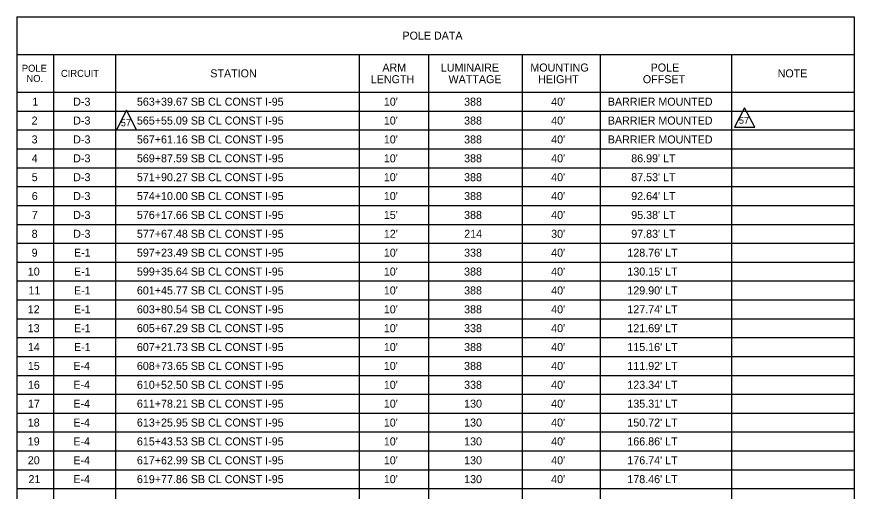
# Model space of a CAD drawing. Extents: x -818.1 to -802.4, y -2221.2 to -2187.7.
# Drawn here: x -817.38 to -810.06, y -2191.84 to -2187.69 of the extents above; entities that cross this region are included whole.
import ezdxf

# ---------------------------------------------------------------- set-up
doc = ezdxf.new("R2010")
doc.units = 0
for name, color, linetype in [('Cloud_dp', 7, 'Continuous'), ('SumBoxBorder_dp', 7, 'Continuous'), ('SumBoxLines_dp', 7, 'Continuous'), ('SumBoxLinesMin_dp', 7, 'Continuous'), ('TextLabel', 7, 'Continuous')]:
    doc.layers.add(name, color=color, linetype=linetype)

msp = doc.modelspace()

# ---------------------------------------------------------------- linework, layer by layer
at = {"layer": 'Cloud_dp'}
for points in [[(-816.4166, -2188.5096), (-816.5046, -2188.6791), (-816.3286, -2188.6791)], [(-811.0144, -2188.4885), (-811.1024, -2188.6581), (-810.9263, -2188.6581)]]:
    msp.add_lwpolyline(points, close=True, dxfattribs=at)
at = {"layer": 'SumBoxBorder_dp'}
for p, q in [((-817.3764, -2187.6917), (-810.0564, -2187.6917)), ((-817.3764, -2187.6917), (-817.3764, -2195.9417)), ((-810.0564, -2187.6917), (-810.0564, -2195.9417)), ((-810.0564, -2187.6917), (-810.0564, -2195.9417)), ((-817.3764, -2188.0217), (-810.0564, -2188.0217)), ((-817.3764, -2188.0217), (-810.0564, -2188.0217))]:
    msp.add_line(p, q, dxfattribs=at)
at = {"layer": 'SumBoxLines_dp'}
for p, q in [((-817.0539, -2188.0217), (-817.0539, -2195.9417)), ((-817.0539, -2188.0217), (-817.0539, -2195.9417)), ((-816.5139, -2188.0217), (-816.5139, -2195.9417)), ((-816.5139, -2188.0217), (-816.5139, -2195.9417)), ((-814.3839, -2188.0217), (-814.3839, -2193.9617)), ((-814.3839, -2188.0217), (-814.3839, -2195.9417)), ((-813.7764, -2188.0217), (-813.7764, -2195.9417)), ((-813.7764, -2188.0217), (-813.7764, -2195.9417)), ((-812.9589, -2188.0217), (-812.9589, -2195.9417)), ((-812.9589, -2188.0217), (-812.9589, -2195.9417)), ((-812.2764, -2188.0217), (-812.2764, -2195.9417)), ((-812.2764, -2188.0217), (-812.2764, -2195.9417)), ((-811.1289, -2188.0217), (-811.1289, -2195.9417)), ((-811.1289, -2188.0217), (-811.1289, -2195.9417)), ((-817.3764, -2188.3517), (-810.0564, -2188.3517))]:
    msp.add_line(p, q, dxfattribs=at)
at = {"layer": 'SumBoxLinesMin_dp'}
for p, q in [((-817.3764, -2188.3517), (-810.0564, -2188.3517)), ((-817.3764, -2188.5167), (-810.0564, -2188.5167)), ((-817.3764, -2188.5167), (-810.0564, -2188.5167)), ((-817.3764, -2188.6817), (-810.0564, -2188.6817)), ((-817.3764, -2188.6817), (-810.0564, -2188.6817)), ((-817.3764, -2188.8467), (-810.0564, -2188.8467)), ((-817.3764, -2188.8467), (-810.0564, -2188.8467)), ((-817.3764, -2189.0117), (-810.0564, -2189.0117)), ((-817.3764, -2189.0117), (-810.0564, -2189.0117)), ((-817.3764, -2189.1767), (-810.0564, -2189.1767)), ((-817.3764, -2189.1767), (-810.0564, -2189.1767)), ((-817.3764, -2189.3417), (-810.0564, -2189.3417)), ((-817.3764, -2189.3417), (-810.0564, -2189.3417)), ((-817.3764, -2189.5067), (-810.0564, -2189.5067)), ((-817.3764, -2189.5067), (-810.0564, -2189.5067)), ((-817.3764, -2189.6717), (-810.0564, -2189.6717)), ((-817.3764, -2189.6717), (-810.0564, -2189.6717)), ((-817.3764, -2189.8367), (-810.0564, -2189.8367)), ((-817.3764, -2189.8367), (-810.0564, -2189.8367)), ((-817.3764, -2190.0017), (-810.0564, -2190.0017)), ((-817.3764, -2190.0017), (-810.0564, -2190.0017)), ((-817.3764, -2190.1667), (-810.0564, -2190.1667)), ((-817.3764, -2190.1667), (-810.0564, -2190.1667)), ((-817.3764, -2190.3317), (-810.0564, -2190.3317)), ((-817.3764, -2190.3317), (-810.0564, -2190.3317)), ((-817.3764, -2190.4967), (-810.0564, -2190.4967)), ((-817.3764, -2190.4967), (-810.0564, -2190.4967)), ((-817.3764, -2190.6617), (-810.0564, -2190.6617)), ((-817.3764, -2190.6617), (-810.0564, -2190.6617)), ((-817.3764, -2190.8267), (-810.0564, -2190.8267)), ((-817.3764, -2190.8267), (-810.0564, -2190.8267)), ((-817.3764, -2190.9917), (-810.0564, -2190.9917)), ((-817.3764, -2190.9917), (-810.0564, -2190.9917)), ((-817.3764, -2191.1567), (-810.0564, -2191.1567)), ((-817.3764, -2191.1567), (-810.0564, -2191.1567)), ((-817.3764, -2191.3217), (-810.0564, -2191.3217)), ((-817.3764, -2191.3217), (-810.0564, -2191.3217)), ((-817.3764, -2191.4867), (-810.0564, -2191.4867)), ((-817.3764, -2191.4867), (-810.0564, -2191.4867)), ((-817.3764, -2191.6517), (-810.0564, -2191.6517)), ((-817.3764, -2191.6517), (-810.0564, -2191.6517)), ((-817.3764, -2191.8167), (-810.0564, -2191.8167)), ((-817.3764, -2191.8167), (-810.0564, -2191.8167))]:
    msp.add_line(p, q, dxfattribs=at)

# ---------------------------------------------------------------- texts
at = {"layer": 'Cloud_dp'}
for p in [(-816.4673, -2188.6489), (-811.0651, -2188.6279)]:
    msp.add_text('57', height=0.06, dxfattribs=at).set_placement(p)
at = {"layer": 'TextLabel'}
for s, height, p in [('POLE DATA', 0.07, (-814.0053, -2187.8917)), ('POLE', 0.06125, (-817.3318, -2188.1727)), ('CIRCUIT', 0.06125, (-816.9898, -2188.2173)), ('STATION', 0.07, (-815.6847, -2188.2217)), ('ARM', 0.07, (-814.1806, -2188.1707)), ('LUMINAIRE', 0.07, (-813.6703, -2188.1707)), ('MOUNTING', 0.07, (-812.8873, -2188.1707)), ('POLE', 0.07, (-811.8359, -2188.1707)), ('NOTE', 0.07, (-810.7259, -2188.2217)), ('NO.', 0.06125, (-817.2918, -2188.2619)), ('LENGTH', 0.07, (-814.2821, -2188.2727)), ('WATTAGE', 0.07, (-813.6025, -2188.2727)), ('HEIGHT', 0.07, (-812.8191, -2188.2727)), ('OFFSET', 0.07, (-811.9041, -2188.2727)), ('1', 0.07, (-817.2398, -2188.4692)), ('D-3', 0.07, (-816.8831, -2188.4692)), ('563+39.67 SB CL CONST I-95', 0.07, (-816.3263, -2188.4692)), ("10'", 0.07, (-814.1681, -2188.4692)), ('388', 0.07, (-813.4665, -2188.4692)), ("40'", 0.07, (-812.7056, -2188.4692)), ('BARRIER MOUNTED', 0.07, (-812.2105, -2188.4692)), ('2', 0.07, (-817.2465, -2188.6342)), ('D-3', 0.07, (-816.8831, -2188.6342)), ('565+55.09 SB CL CONST I-95', 0.07, (-816.3263, -2188.6342)), ("10'", 0.07, (-814.1681, -2188.6342)), ('388', 0.07, (-813.4665, -2188.6342)), ("40'", 0.07, (-812.7056, -2188.6342)), ('BARRIER MOUNTED', 0.07, (-812.2105, -2188.6342)), ('3', 0.07, (-817.2466, -2188.7992)), ('D-3', 0.07, (-816.8831, -2188.7992)), ('567+61.16 SB CL CONST I-95', 0.07, (-816.3263, -2188.7992)), ("10'", 0.07, (-814.1681, -2188.7992)), ('388', 0.07, (-813.4665, -2188.7992)), ("40'", 0.07, (-812.7056, -2188.7992)), ('BARRIER MOUNTED', 0.07, (-812.2105, -2188.7992)), ('4', 0.07, (-817.2452, -2188.9642)), ('D-3', 0.07, (-816.8831, -2188.9642)), ('569+87.59 SB CL CONST I-95', 0.07, (-816.3263, -2188.9642)), ("10'", 0.07, (-814.1681, -2188.9642)), ('388', 0.07, (-813.4665, -2188.9642)), ("40'", 0.07, (-812.7056, -2188.9642)), ("86.99' LT", 0.07, (-812.0057, -2188.9642)), ('5', 0.07, (-817.2457, -2189.1292)), ('D-3', 0.07, (-816.8831, -2189.1292)), ('571+90.27 SB CL CONST I-95', 0.07, (-816.3263, -2189.1292)), ("10'", 0.07, (-814.1681, -2189.1292)), ('388', 0.07, (-813.4665, -2189.1292)), ("40'", 0.07, (-812.7056, -2189.1292)), ("87.53' LT", 0.07, (-812.0057, -2189.1292)), ('6', 0.07, (-817.2451, -2189.2942)), ('D-3', 0.07, (-816.8831, -2189.2942)), ('574+10.00 SB CL CONST I-95', 0.07, (-816.3263, -2189.2942)), ("10'", 0.07, (-814.1681, -2189.2942)), ('388', 0.07, (-813.4665, -2189.2942)), ("40'", 0.07, (-812.7056, -2189.2942)), ("92.64' LT", 0.07, (-812.0057, -2189.2942)), ('7', 0.07, (-817.2445, -2189.4592)), ('D-3', 0.07, (-816.8831, -2189.4592)), ('576+17.66 SB CL CONST I-95', 0.07, (-816.3263, -2189.4592)), ("15'", 0.07, (-814.1681, -2189.4592)), ('388', 0.07, (-813.4665, -2189.4592)), ("40'", 0.07, (-812.7056, -2189.4592)), ("95.38' LT", 0.07, (-812.0057, -2189.4592)), ('8', 0.07, (-817.2463, -2189.6242)), ('D-3', 0.07, (-816.8831, -2189.6242)), ('577+67.48 SB CL CONST I-95', 0.07, (-816.3263, -2189.6242)), ("12'", 0.07, (-814.1681, -2189.6242)), ('214', 0.07, (-813.4654, -2189.6242)), ("30'", 0.07, (-812.7056, -2189.6242)), ("97.83' LT", 0.07, (-812.0057, -2189.6242)), ('9', 0.07, (-817.2462, -2189.7892)), ('E-1', 0.07, (-816.8763, -2189.7892)), ('597+23.49 SB CL CONST I-95', 0.07, (-816.3263, -2189.7892)), ("10'", 0.07, (-814.1681, -2189.7892)), ('338', 0.07, (-813.4665, -2189.7892)), ("40'", 0.07, (-812.7056, -2189.7892)), ("128.76' LT", 0.07, (-812.0396, -2189.7892)), ('10', 0.07, (-817.2798, -2189.9542)), ('E-1', 0.07, (-816.8763, -2189.9542)), ('599+35.64 SB CL CONST I-95', 0.07, (-816.3263, -2189.9542)), ("10'", 0.07, (-814.1681, -2189.9542)), ('388', 0.07, (-813.4665, -2189.9542)), ("40'", 0.07, (-812.7056, -2189.9542)), ("130.15' LT", 0.07, (-812.0396, -2189.9542)), ('11', 0.07, (-817.2737, -2190.1192)), ('E-1', 0.07, (-816.8763, -2190.1192)), ('601+45.77 SB CL CONST I-95', 0.07, (-816.3263, -2190.1192)), ("10'", 0.07, (-814.1681, -2190.1192)), ('388', 0.07, (-813.4665, -2190.1192)), ("40'", 0.07, (-812.7056, -2190.1192)), ("129.90' LT", 0.07, (-812.0396, -2190.1192)), ('12', 0.07, (-817.2804, -2190.2842)), ('E-1', 0.07, (-816.8763, -2190.2842)), ('603+80.54 SB CL CONST I-95', 0.07, (-816.3263, -2190.2842)), ("10'", 0.07, (-814.1681, -2190.2842)), ('388', 0.07, (-813.4665, -2190.2842)), ("40'", 0.07, (-812.7056, -2190.2842)), ("127.74' LT", 0.07, (-812.0396, -2190.2842)), ('13', 0.07, (-817.2804, -2190.4492)), ('E-1', 0.07, (-816.8763, -2190.4492)), ('605+67.29 SB CL CONST I-95', 0.07, (-816.3263, -2190.4492)), ("10'", 0.07, (-814.1681, -2190.4492)), ('338', 0.07, (-813.4665, -2190.4492)), ("40'", 0.07, (-812.7056, -2190.4492)), ("121.69' LT", 0.07, (-812.0396, -2190.4492)), ('14', 0.07, (-817.279, -2190.6142)), ('E-1', 0.07, (-816.8763, -2190.6142)), ('607+21.73 SB CL CONST I-95', 0.07, (-816.3263, -2190.6142)), ("10'", 0.07, (-814.1681, -2190.6142)), ('388', 0.07, (-813.4665, -2190.6142)), ("40'", 0.07, (-812.7056, -2190.6142)), ("115.16' LT", 0.07, (-812.0396, -2190.6142)), ('15', 0.07, (-817.2795, -2190.7792)), ('E-4', 0.07, (-816.8817, -2190.7792)), ('608+73.65 SB CL CONST I-95', 0.07, (-816.3263, -2190.7792)), ("10'", 0.07, (-814.1681, -2190.7792)), ('388', 0.07, (-813.4665, -2190.7792)), ("40'", 0.07, (-812.7056, -2190.7792)), ("111.92' LT", 0.07, (-812.0396, -2190.7792)), ('16', 0.07, (-817.279, -2190.9442)), ('E-4', 0.07, (-816.8817, -2190.9442)), ('610+52.50 SB CL CONST I-95', 0.07, (-816.3263, -2190.9442)), ("10'", 0.07, (-814.1681, -2190.9442)), ('338', 0.07, (-813.4665, -2190.9442)), ("40'", 0.07, (-812.7056, -2190.9442)), ("123.34' LT", 0.07, (-812.0396, -2190.9442)), ('17', 0.07, (-817.2784, -2191.1092)), ('E-4', 0.07, (-816.8817, -2191.1092)), ('611+78.21 SB CL CONST I-95', 0.07, (-816.3263, -2191.1092)), ("10'", 0.07, (-814.1681, -2191.1092)), ('130', 0.07, (-813.4662, -2191.1092)), ("40'", 0.07, (-812.7056, -2191.1092)), ("135.31' LT", 0.07, (-812.0396, -2191.1092)), ('18', 0.07, (-817.2802, -2191.2742)), ('E-4', 0.07, (-816.8817, -2191.2742)), ('613+25.95 SB CL CONST I-95', 0.07, (-816.3263, -2191.2742)), ("10'", 0.07, (-814.1681, -2191.2742)), ('130', 0.07, (-813.4662, -2191.2742)), ("40'", 0.07, (-812.7056, -2191.2742)), ("150.72' LT", 0.07, (-812.0396, -2191.2742)), ('19', 0.07, (-817.28, -2191.4392)), ('E-4', 0.07, (-816.8817, -2191.4392)), ('615+43.53 SB CL CONST I-95', 0.07, (-816.3263, -2191.4392)), ("10'", 0.07, (-814.1681, -2191.4392)), ('130', 0.07, (-813.4662, -2191.4392)), ("40'", 0.07, (-812.7056, -2191.4392)), ("166.86' LT", 0.07, (-812.0396, -2191.4392)), ('20', 0.07, (-817.2798, -2191.6042)), ('E-4', 0.07, (-816.8817, -2191.6042)), ('617+62.99 SB CL CONST I-95', 0.07, (-816.3263, -2191.6042)), ("10'", 0.07, (-814.1681, -2191.6042)), ('130', 0.07, (-813.4662, -2191.6042)), ("40'", 0.07, (-812.7056, -2191.6042)), ("176.74' LT", 0.07, (-812.0396, -2191.6042)), ('21', 0.07, (-817.2737, -2191.7692)), ('E-4', 0.07, (-816.8817, -2191.7692)), ('619+77.86 SB CL CONST I-95', 0.07, (-816.3263, -2191.7692)), ("10'", 0.07, (-814.1681, -2191.7692)), ('130', 0.07, (-813.4662, -2191.7692)), ("40'", 0.07, (-812.7056, -2191.7692)), ("178.46' LT", 0.07, (-812.0396, -2191.7692))]:
    msp.add_text(s, height=height, dxfattribs=at).set_placement(p)

doc.saveas('drawing.dxf')
